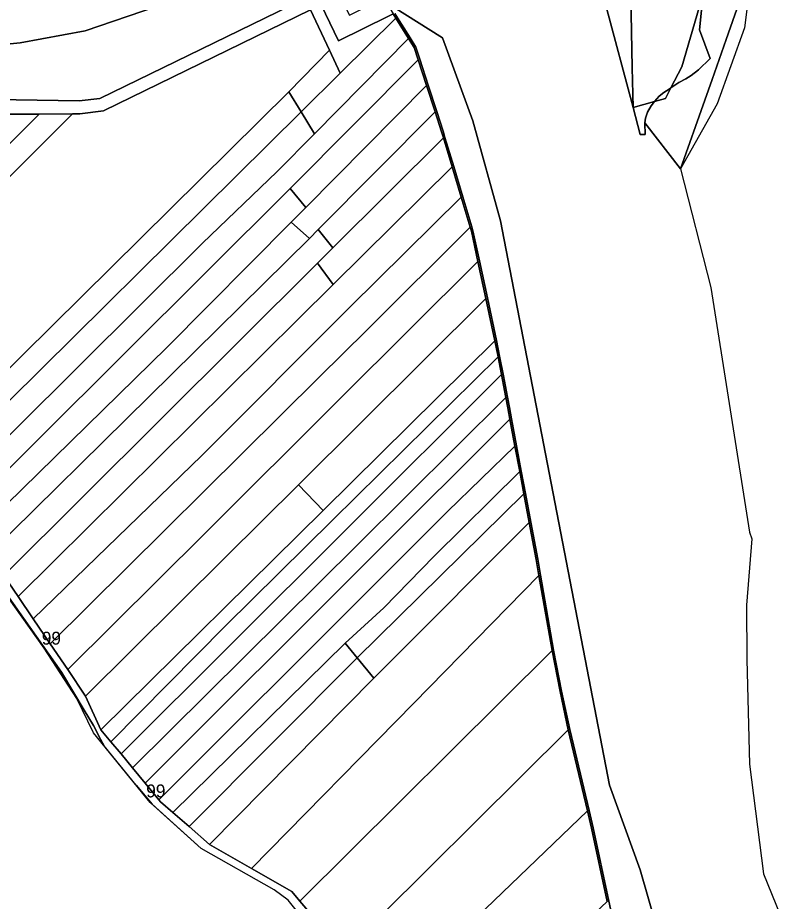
# Model space of a CAD drawing. Extents: x -535894 to -532834, y -1165802 to -1163645.
# Drawn here: x -533262.6 to -532964.2, y -1165246.7 to -1164904.7 of the extents above; entities that cross this region are included whole.
import ezdxf

# ---------------------------------------------------------------- set-up
doc = ezdxf.new("R2010")
doc.units = 0
for name, color, linetype in [('95560013', 7, 'Continuous'), ('95610013', 7, 'Continuous'), ('95630013', 7, 'Continuous'), ('95640013', 7, 'Continuous'), ('95660013', 7, 'Continuous')]:
    doc.layers.add(name, color=color, linetype=linetype)

msp = doc.modelspace()

# ---------------------------------------------------------------- linework, layer by layer
at = {"layer": '95560013'}
for points in [[(-533149.26, -1164901.65), (-533141.88, -1164917.25), (-533157.58, -1164933.38), (-533260.52, -1165035.2), (-533294.68, -1165069.27), (-533316.06, -1165016.63), (-533241.31, -1164941.86), (-533238.5, -1164941.84), (-533229.28, -1164940.77)], [(-533149.26, -1164901.65), (-533145.13, -1164899.63), (-533138.32, -1164913.61), (-533119.06, -1164904.11), (-533117.14, -1164903.15), (-533116.11, -1164904.82), (-533137.69, -1164926.13), (-533141.88, -1164917.25)], [(-533116.11, -1164904.82), (-533111.26, -1164912.65), (-533147.66, -1164949.6), (-533152.84, -1164941.12), (-533137.69, -1164926.13)], [(-533111.26, -1164912.65), (-533109.04, -1164916.24), (-533107.52, -1164920.92), (-533157.09, -1164970.71), (-533286.88, -1165099.92), (-533295.36, -1165095.55), (-533290.36, -1165090.63), (-533286.76, -1165088.76), (-533287.25, -1165087.56), (-533191.02, -1164991.97), (-533162.21, -1164964.36), (-533147.66, -1164949.6)], [(-533141.88, -1164917.25), (-533137.69, -1164926.13), (-533152.84, -1164941.12), (-533157.58, -1164933.38)], [(-533107.52, -1164920.92), (-533104.27, -1164930.9), (-533151.05, -1164978.13), (-533157.09, -1164970.71)], [(-533157.58, -1164933.38), (-533152.84, -1164941.12), (-533291.2, -1165077.84), (-533294.68, -1165069.27), (-533260.52, -1165035.2)], [(-533104.27, -1164930.9), (-533100.95, -1164941.1), (-533146.17, -1164986.67), (-533149.64, -1164990.09), (-533156.74, -1164983.77), (-533151.05, -1164978.13)], [(-533267.6, -1164942.04), (-533254.19, -1164941.95), (-533319.84, -1165007.34), (-533323.61, -1164998.03)], [(-533254.19, -1164941.95), (-533241.31, -1164941.86), (-533316.06, -1165016.63), (-533316.16, -1165016.4), (-533319.84, -1165007.34)], [(-533152.84, -1164941.12), (-533147.66, -1164949.6), (-533162.21, -1164964.36), (-533191.02, -1164991.97), (-533287.25, -1165087.56), (-533291.2, -1165077.84)], [(-533100.95, -1164941.1), (-533098.44, -1164948.8), (-533097.74, -1164951.15), (-533140.53, -1164993.73), (-533146.17, -1164986.67)], [(-533097.74, -1164951.15), (-533094.38, -1164962.37), (-533140.42, -1165007.98), (-533146.54, -1164999.72), (-533140.53, -1164993.73)], [(-533094.38, -1164962.37), (-533090.86, -1164974.13), (-533134.01, -1165016.65), (-533191.31, -1165074.15), (-533256.52, -1165137.33), (-533262.35, -1165128.75), (-533140.42, -1165007.98)], [(-533157.09, -1164970.71), (-533151.05, -1164978.13), (-533156.74, -1164983.77), (-533204.88, -1165032.37), (-533279.36, -1165105.17), (-533286.88, -1165099.92)], [(-533090.86, -1164974.13), (-533087.36, -1164985.79), (-533127.44, -1165025.54), (-533145.8, -1165043.76), (-533249.93, -1165147.04), (-533256.52, -1165137.33), (-533191.31, -1165074.15), (-533134.01, -1165016.65)], [(-533156.74, -1164983.77), (-533149.64, -1164990.09), (-533273.82, -1165112.38), (-533279.36, -1165105.17), (-533204.88, -1165032.37)], [(-533149.64, -1164990.09), (-533146.17, -1164986.67), (-533140.53, -1164993.73), (-533146.54, -1164999.72), (-533267.92, -1165120.55), (-533270.77, -1165116.36), (-533273.82, -1165112.38)], [(-533087.36, -1164985.79), (-533086.92, -1164987.26), (-533084.4, -1164998.97), (-533137.64, -1165051.96), (-533190.56, -1165104.63), (-533243.17, -1165156.99), (-533249.93, -1165147.04), (-533145.8, -1165043.76), (-533127.44, -1165025.54)], [(-533140.42, -1165007.98), (-533262.35, -1165128.75), (-533267.92, -1165120.55), (-533146.54, -1164999.72)], [(-533084.4, -1164998.97), (-533081.32, -1165013.31), (-533153.89, -1165085.42), (-533182.06, -1165113.41), (-533236.25, -1165167.26), (-533243.17, -1165156.99), (-533190.56, -1165104.63), (-533137.64, -1165051.96)], [(-533081.32, -1165013.31), (-533077.78, -1165029.77), (-533144.31, -1165095.36), (-533153.89, -1165085.42)], [(-533077.78, -1165029.77), (-533076.61, -1165035.87), (-533140.65, -1165099.16), (-533182.05, -1165140.09), (-533226.46, -1165184.88), (-533230.42, -1165180.24), (-533144.31, -1165095.36)], [(-533144.31, -1165095.36), (-533230.42, -1165180.24), (-533236.25, -1165167.26), (-533182.06, -1165113.41), (-533153.89, -1165085.42)]]:
    msp.add_lwpolyline(points, close=True, dxfattribs=at)
at = {"layer": '95610013'}
for points in [[(-533076.61, -1165035.87), (-533075.28, -1165042.82), (-533136.31, -1165103.66), (-533222.54, -1165189.63), (-533226.46, -1165184.88), (-533182.05, -1165140.09), (-533140.65, -1165099.16)], [(-533075.28, -1165042.82), (-533073.57, -1165051.71), (-533131.26, -1165108.9), (-533218.08, -1165195.01), (-533222.54, -1165189.63), (-533136.31, -1165103.66)], [(-533073.57, -1165051.71), (-533072.81, -1165055.68), (-533072, -1165060.03), (-533126.21, -1165114.14), (-533213.17, -1165200.95), (-533218.08, -1165195.01), (-533131.26, -1165108.9)], [(-533072, -1165060.03), (-533070.04, -1165070.55), (-533096.16, -1165095.82), (-533120.47, -1165120.09), (-533125.29, -1165124.9), (-533207.89, -1165207.35), (-533213.17, -1165200.95), (-533126.21, -1165114.14)], [(-533070.04, -1165070.55), (-533068.21, -1165080.3), (-533101.38, -1165113.14), (-533120.76, -1165133.08), (-533135.8, -1165146.72), (-533202.5, -1165212.26), (-533207.25, -1165208.12), (-533207.89, -1165207.35), (-533125.29, -1165124.9), (-533120.47, -1165120.09), (-533096.16, -1165095.82)], [(-533068.21, -1165080.3), (-533066.59, -1165088.96), (-533131.14, -1165152.47), (-533135.8, -1165146.72), (-533120.76, -1165133.08), (-533101.38, -1165113.14)], [(-533066.59, -1165088.96), (-533064.51, -1165100.09), (-533119.77, -1165155.35), (-533124.7, -1165160.3), (-533131.14, -1165152.47)], [(-533064.51, -1165100.09), (-533061.85, -1165114.35), (-533060.76, -1165120.61), (-533109.26, -1165169.99), (-533172.08, -1165233.95), (-533188.3, -1165224.67), (-533124.7, -1165160.3), (-533119.77, -1165155.35)], [(-533060.76, -1165120.61), (-533055.7, -1165149.58), (-533153.35, -1165246.57), (-533156.44, -1165242.91), (-533172.08, -1165233.95), (-533109.26, -1165169.99)], [(-533131.14, -1165152.47), (-533196.24, -1165217.73), (-533202.5, -1165212.26), (-533135.8, -1165146.72)], [(-533124.7, -1165160.3), (-533188.3, -1165224.67), (-533196.24, -1165217.73), (-533131.14, -1165152.47)], [(-533055.7, -1165149.58), (-533052.58, -1165165.52), (-533049.49, -1165180.28), (-533139.66, -1165269.87), (-533140.71, -1165266.61), (-533148.1, -1165252.82), (-533153.35, -1165246.57)], [(-533049.49, -1165180.28), (-533041.97, -1165211.69), (-533127.5, -1165293.84), (-533133.87, -1165286.06), (-533136.9, -1165278.38), (-533139.66, -1165269.87)], [(-533041.97, -1165211.69), (-533040.38, -1165218.35), (-533034.31, -1165246.78), (-533108.53, -1165316.98), (-533127.5, -1165293.84)]]:
    msp.add_lwpolyline(points, close=True, dxfattribs=at)
at = {"layer": '95630013'}
msp.add_lwpolyline([(-532990.84, -1164820.26), (-532986.56, -1164818.1), (-532980.17, -1164845.09), (-532977.31, -1164877.84), (-532981.22, -1164908.52), (-532991.79, -1164937.99), (-533005.91, -1164963.1), (-532996.56, -1164936.58), (-532993.75, -1164928.6), (-532988.28, -1164913.08), (-532983.25, -1164898.77), (-532982.29, -1164880.52), (-532983.21, -1164860.62)], close=True, dxfattribs=at)
for points in [[(-533192.2, -1164894.47), (-533236.41, -1164909.7), (-533261.61, -1164914.36), (-533291.28, -1164917.31), (-533340.78, -1164912.67), (-533361.33, -1164907.54), (-533389.23, -1164897.67)], [(-532983.25, -1164898.77), (-532988.28, -1164913.08), (-532993.75, -1164928.6), (-532996.56, -1164936.58), (-533005.91, -1164963.1), (-533019.74, -1164945.35), (-533019.5, -1164943.61), (-533018.74, -1164941.21), (-533017.27, -1164938.72), (-533016.06, -1164937.15), (-533011.8, -1164935.96), (-533009.67, -1164931.84), (-533006.56, -1164929.76), (-533003.92, -1164928.32), (-533001.85, -1164927.06), (-532998.95, -1164924.85), (-532994.46, -1164920.43), (-532998.63, -1164909.37), (-532997.02, -1164894.02)], [(-533035.02, -1164899.39), (-533024.33, -1164939.46), (-533021.57, -1164949.83), (-533019.65, -1164949.83), (-533019.75, -1164945.44), (-533019.74, -1164945.35), (-533005.91, -1164963.1), (-532994.2, -1165009.04), (-532979.21, -1165103.79), (-532978.36, -1165106.4), (-532980.41, -1165132.1), (-532980.24, -1165153.13), (-532979.22, -1165193.65), (-532973.81, -1165236.01), (-532964.21, -1165259.48)], [(-533011.43, -1165270.01), (-533021.55, -1165234.47), (-533033.46, -1165201.68), (-533075.69, -1164983.34), (-533086.39, -1164944.59), (-533098.11, -1164912.42), (-533117.22, -1164900.45)]]:
    msp.add_lwpolyline(points, dxfattribs=at)
at = {"layer": '95640013'}
for points in [[(-533013.9, -1164850.14), (-533013.81, -1164850.1), (-533010.63, -1164859.43), (-533010.45, -1164859.97), (-533010.66, -1164860.03), (-533003.87, -1164880.13), (-532999.62, -1164888.13), (-532997.96, -1164892.84), (-532998.67, -1164900.76), (-533005.49, -1164923.73), (-533009.67, -1164931.84), (-533010.36, -1164932.29), (-533012.47, -1164933.65), (-533014.17, -1164935.04), (-533016.06, -1164937.15), (-533024.33, -1164939.46), (-533024.62, -1164923.92), (-533025.13, -1164896.12), (-533015.73, -1164893.02), (-533017.56, -1164884.6), (-533021.51, -1164873.18), (-533018.63, -1164862.11), (-533016.75, -1164854.92), (-533014.78, -1164845.11)], [(-533122.04, -1164897.68), (-533119.37, -1164896.37), (-533119.82, -1164898.82), (-533117.14, -1164903.15), (-533119.06, -1164904.11), (-533138.32, -1164913.61), (-533145.13, -1164899.63), (-533137.86, -1164896.07), (-533136.13, -1164899.58), (-533135.74, -1164900.39), (-533134.16, -1164903.63), (-533132.1, -1164902.62)], [(-532997.96, -1164892.84), (-532997.55, -1164893.98), (-532997.02, -1164894.02), (-532998.63, -1164909.37), (-532994.46, -1164920.43), (-532998.95, -1164924.85), (-533001.85, -1164927.06), (-533003.92, -1164928.32), (-533006.56, -1164929.76), (-533009.67, -1164931.84), (-533005.49, -1164923.73), (-532998.67, -1164900.76)], [(-533035.02, -1164899.39), (-533025.13, -1164896.12), (-533024.62, -1164923.92), (-533024.33, -1164939.46)], [(-533009.67, -1164931.84), (-533011.8, -1164935.96), (-533016.06, -1164937.15), (-533014.17, -1164935.04), (-533012.47, -1164933.65), (-533010.36, -1164932.29)], [(-533016.06, -1164937.15), (-533017.27, -1164938.72), (-533018.74, -1164941.21), (-533019.5, -1164943.61), (-533019.74, -1164945.35), (-533019.75, -1164945.44), (-533019.65, -1164949.83), (-533021.57, -1164949.83), (-533024.33, -1164939.46)]]:
    msp.add_lwpolyline(points, close=True, dxfattribs=at)
for points in [[(-533408.38, -1164903.25), (-533391.45, -1164912.18), (-533348.75, -1164931.67), (-533346.78, -1164932.24), (-533341.76, -1164933.66), (-533339.52, -1164934.29), (-533328.53, -1164937.19), (-533318.96, -1164935.26), (-533312.12, -1164935.66), (-533238.8, -1164936.84), (-533230.7, -1164935.9), (-533147.32, -1164895.13)], [(-533147.32, -1164895.13), (-533230.7, -1164935.9), (-533238.8, -1164936.84), (-533312.12, -1164935.66), (-533318.96, -1164935.26), (-533328.53, -1164937.19), (-533339.52, -1164934.29), (-533341.76, -1164933.66), (-533346.78, -1164932.24), (-533348.75, -1164931.67), (-533391.45, -1164912.18), (-533408.38, -1164903.25)], [(-533389.23, -1164897.67), (-533361.33, -1164907.54), (-533340.78, -1164912.67), (-533291.28, -1164917.31), (-533261.61, -1164914.36), (-533236.41, -1164909.7), (-533192.2, -1164894.47)], [(-533149.26, -1164901.65), (-533229.28, -1164940.77), (-533238.5, -1164941.84), (-533241.31, -1164941.86), (-533254.19, -1164941.95), (-533267.6, -1164942.04)], [(-533117.22, -1164900.45), (-533098.11, -1164912.42), (-533086.39, -1164944.59), (-533075.69, -1164983.34), (-533033.46, -1165201.68), (-533021.55, -1165234.47), (-533011.43, -1165270.01)], [(-533034.31, -1165246.78), (-533040.38, -1165218.35), (-533041.97, -1165211.69), (-533049.49, -1165180.28), (-533052.58, -1165165.52), (-533055.7, -1165149.58), (-533060.76, -1165120.61), (-533061.85, -1165114.35), (-533064.51, -1165100.09), (-533066.59, -1165088.96), (-533068.21, -1165080.3), (-533070.04, -1165070.55), (-533072, -1165060.03), (-533072.81, -1165055.68), (-533073.57, -1165051.71), (-533075.28, -1165042.82), (-533076.61, -1165035.87), (-533077.78, -1165029.77), (-533081.32, -1165013.31), (-533084.4, -1164998.97), (-533086.92, -1164987.26), (-533087.36, -1164985.79), (-533090.86, -1164974.13), (-533094.38, -1164962.37), (-533097.74, -1164951.15), (-533098.44, -1164948.8), (-533100.95, -1164941.1), (-533104.27, -1164930.9), (-533107.52, -1164920.92), (-533109.04, -1164916.24), (-533111.26, -1164912.65), (-533116.11, -1164904.82), (-533117.14, -1164903.15)], [(-533151.29, -1165254.43), (-533157.9, -1165246.26), (-533163.24, -1165242.28), (-533191.59, -1165226.21), (-533211.21, -1165208.48), (-533233.16, -1165181.49), (-533239.66, -1165168.21), (-533252.35, -1165148.73), (-533279.97, -1165109.85)], [(-533267.92, -1165120.55), (-533262.35, -1165128.75), (-533256.52, -1165137.33), (-533249.93, -1165147.04), (-533243.17, -1165156.99), (-533236.25, -1165167.26), (-533230.42, -1165180.24), (-533226.46, -1165184.88), (-533222.54, -1165189.63), (-533218.08, -1165195.01), (-533213.17, -1165200.95), (-533207.89, -1165207.35), (-533207.25, -1165208.12), (-533202.5, -1165212.26), (-533196.24, -1165217.73), (-533188.3, -1165224.67), (-533172.08, -1165233.95), (-533156.44, -1165242.91), (-533153.35, -1165246.57), (-533148.1, -1165252.82)]]:
    msp.add_lwpolyline(points, dxfattribs=at)
at = {"layer": '95660013'}
for points in [[(-532977.31, -1164877.84), (-532981.22, -1164908.52), (-532991.79, -1164937.99), (-533005.91, -1164963.1), (-532994.2, -1165009.04), (-532979.21, -1165103.79), (-532978.36, -1165106.4), (-532980.41, -1165132.1), (-532980.24, -1165153.13), (-532979.22, -1165193.65), (-532973.81, -1165236.01), (-532964.21, -1165259.48)], [(-533116.533, -1164902.995), (-533115.501, -1164904.659), (-533110.648, -1164912.493), (-533108.431, -1164916.081), (-533106.908, -1164920.756), (-533103.663, -1164930.745), (-533100.34, -1164940.944), (-533097.835, -1164948.637), (-533097.131, -1164950.989), (-533093.771, -1164962.208), (-533090.249, -1164973.968), (-533086.749, -1164985.636), (-533086.307, -1164987.103), (-533083.786, -1164998.813), (-533080.702, -1165013.15), (-533077.17, -1165029.609), (-533075.998, -1165035.716), (-533074.668, -1165042.665), (-533072.958, -1165051.547), (-533072.194, -1165055.526), (-533071.38, -1165059.872), (-533069.42, -1165070.392), (-533067.597, -1165080.142), (-533065.975, -1165088.803), (-533063.892, -1165099.931), (-533061.232, -1165114.191), (-533060.138, -1165120.449), (-533055.079, -1165149.423), (-533051.963, -1165165.364), (-533048.865, -1165180.125), (-533041.352, -1165211.535), (-533039.758, -1165218.191), (-533033.684, -1165246.624), (-533025.608, -1165284.384)], [(-533025.608, -1165284.384), (-533033.684, -1165246.624), (-533039.758, -1165218.191), (-533041.352, -1165211.535), (-533048.865, -1165180.125), (-533051.963, -1165165.364), (-533055.079, -1165149.423), (-533060.138, -1165120.449), (-533061.232, -1165114.191), (-533063.892, -1165099.931), (-533065.975, -1165088.803), (-533067.597, -1165080.142), (-533069.42, -1165070.392), (-533071.38, -1165059.872), (-533072.194, -1165055.526), (-533072.958, -1165051.547), (-533074.668, -1165042.665), (-533075.998, -1165035.716), (-533077.17, -1165029.609), (-533080.702, -1165013.15), (-533083.786, -1164998.813), (-533086.307, -1164987.103), (-533086.749, -1164985.636), (-533090.249, -1164973.968), (-533093.771, -1164962.208), (-533097.131, -1164950.989), (-533097.835, -1164948.637), (-533100.34, -1164940.944), (-533103.663, -1164930.745), (-533106.908, -1164920.756), (-533108.431, -1164916.081), (-533110.648, -1164912.493), (-533115.501, -1164904.659), (-533116.533, -1164902.995)], [(-533151.29, -1165254.43), (-533157.9, -1165246.26), (-533163.24, -1165242.28), (-533191.59, -1165226.21), (-533210.519, -1165209.105), (-533216.681, -1165201.753), (-533229.131, -1165186.444), (-533230.475, -1165183.857), (-533233.21, -1165178.59), (-533236.776, -1165172.663), (-533245.64, -1165157.93), (-533276.71, -1165113.99)]]:
    msp.add_lwpolyline(points, dxfattribs=at)
for points in [[(-533230.475, -1165183.857), (-533229.131, -1165186.444), (-533233.16, -1165181.49), (-533239.66, -1165168.21), (-533252.35, -1165148.73), (-533277.344, -1165113.547), (-533276.71, -1165113.99), (-533245.64, -1165157.93), (-533236.776, -1165172.663), (-533233.21, -1165178.59)], [(-533216.681, -1165201.753), (-533210.519, -1165209.105), (-533211.21, -1165208.48)]]:
    msp.add_lwpolyline(points, close=True, dxfattribs=at)

# ---------------------------------------------------------------- texts
for rotation, p in [(360, (-533253.238, -1165147.333)), (0, (-533212.803, -1165206.446))]:
    msp.add_text('99', height=5, rotation=rotation, dxfattribs=at).set_placement(p)

doc.saveas('drawing.dxf')
